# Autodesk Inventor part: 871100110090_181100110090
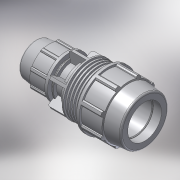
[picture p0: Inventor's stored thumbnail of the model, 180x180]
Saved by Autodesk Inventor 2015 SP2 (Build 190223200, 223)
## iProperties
Created: 2017-02
Part Number: 871100110090_181100110090
Material: PVC-Piping
Description: PLASSON REDUCING COUPLER 110-90
Document SubType Name: Modeling
Designer: KIM
Mass: 92.6774 g
Surface Area: 199.44 cm^2
Volume: 66.1981 cm^3
Density: 1.4 g/cm^3
Appearance: Smooth - White
Author: KIM
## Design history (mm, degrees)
derived "87110.ipt"
feature "Solid1::87110.ipt"
tag "TaggingFeature1"
body "Solid1"
other parameters: "d4" = 31.66667, "d5" = 54.28571, "d7" = 181, "d9" = 54.28571, "d11" = 5.42857, "d12" = 144.8, "d13" = 120 deg, "d14" = 143, "d15" = 6 deg, "d16" = 162.9, "d18" = 5.5, "d19" = 35 deg, "d20" = 17.5 deg, "d21" = 168.33, "d23" = 0, "d25" = 360 deg, "d27" = 3.62, "d42" = 83.6, "d46" = 2.2, "d52" = 54.28571, "d53" = 8 deg, "d54" = 196, "d56" = 117, "d58" = 99, "d59" = 81, "d60" = 136.8, "d61" = 121.6, "d62" = 47.5, "d63" = 68.4, "d64" = 120 deg, "d65" = 152, "d68" = 27.14286, "d74" = 141.36, "d75" = 35 deg, "d76" = 17.5 deg, "d78" = 0, "d80" = 360 deg, "d85" = 3.04, "d88" = 1.8, "d93" = 161, "d94" = 126.7, "d98" = 10.13333, "d99" = 0, "d100" = 7.24, "d102" = 360 deg, "d104" = 2, "d106" = 0, "d107" = 10.13333, "d108" = 0, "d109" = 10.13333, "d110" = 0, "d111" = 3.11667, "d112" = 3.11667, "d113" = 3.11667, "d114" = 3.70429, "d116" = 3.70429, "d119" = 7.40857, "d125" = 159.642, "E_" = 181, "l_" = 196, "E_1" = 152, "l_1" = 161, "d96" = 9.35, "d115" = 37.04286
